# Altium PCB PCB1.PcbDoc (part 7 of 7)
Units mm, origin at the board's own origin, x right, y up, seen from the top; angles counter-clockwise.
Board outline 139.9 x 46.81 mm, 2 copper layers (Top Layer, Bottom Layer); 0 components, 100 nets, 100 pads, 0 vias.
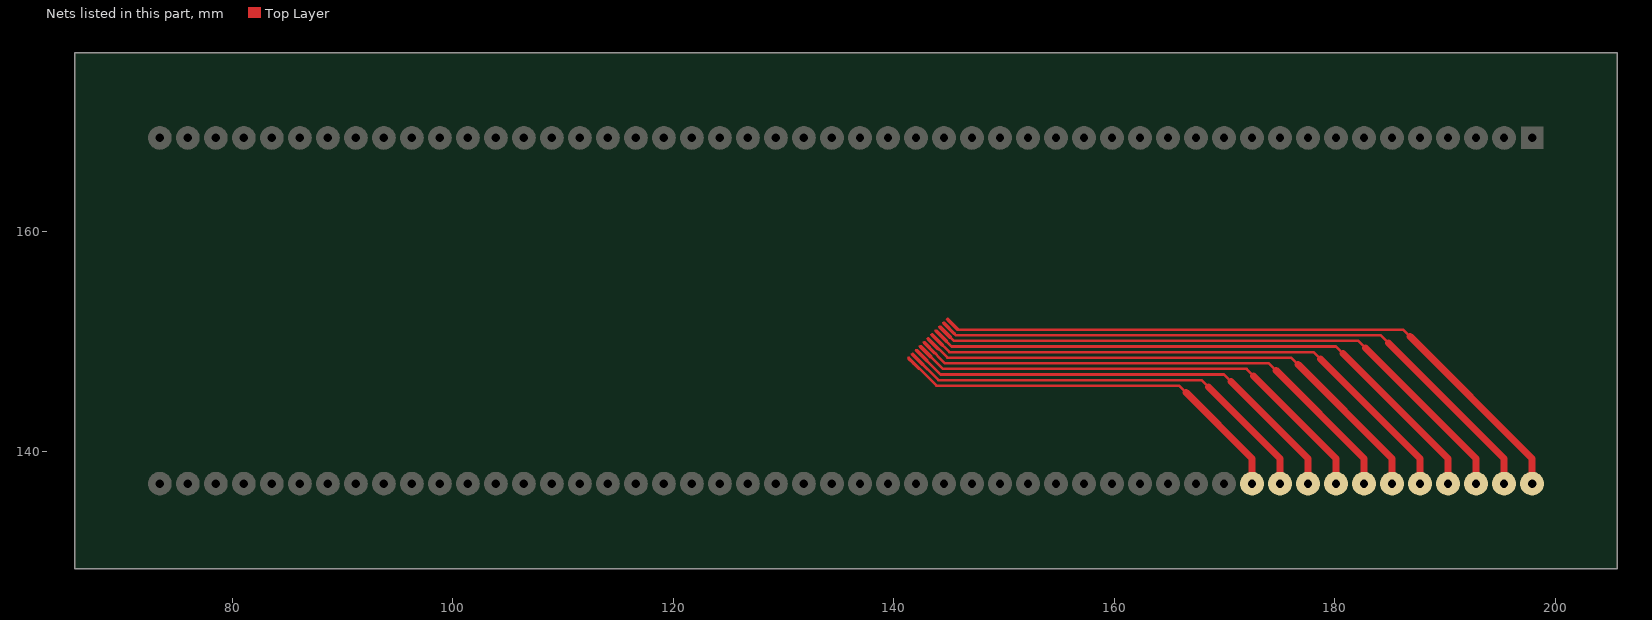
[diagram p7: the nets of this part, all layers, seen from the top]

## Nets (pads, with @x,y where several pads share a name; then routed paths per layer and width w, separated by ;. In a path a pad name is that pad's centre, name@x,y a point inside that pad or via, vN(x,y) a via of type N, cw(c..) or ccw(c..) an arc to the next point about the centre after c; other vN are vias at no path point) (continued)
$Net89: pad.1@172.487,137.086 | length 60.5
  Top Layer w0.03: 141.243,148.47 141.512,148.47 ; 141.245,148.455 141.527,148.455 ; 141.248,148.44 141.542,148.44 ; 141.255,148.424 141.558,148.424 ; 141.258,148.516 141.466,148.516 ; 141.268,148.409 141.573,148.409 ; 141.283,148.394 141.588,148.394 ; 141.283,148.546 141.436,148.546 ; 141.298,148.379 141.603,148.379 ; 141.301,148.561 141.42,148.561 ; 141.314,148.363 141.618,148.363 ; 141.324,148.577 141.397,148.577 ; 141.329,148.348 141.634,148.348 ; 141.344,148.333 141.649,148.333 ; 141.359,148.318 141.664,148.318 ; 141.375,148.302 141.679,148.302 ; 141.39,148.287 141.695,148.287 ; 141.405,148.272 141.71,148.272 ; 141.42,148.257 141.725,148.257 ; 141.436,148.241 141.74,148.241 ; 141.451,148.226 141.756,148.226 ; 141.451,148.531 141.268,148.531 ; 141.466,148.211 141.771,148.211 ; 141.481,148.196 141.786,148.196 ; 141.481,148.501 141.248,148.501 ; 141.497,148.18 141.801,148.18 ; 141.497,148.485 141.243,148.485 ; 141.512,148.165 141.817,148.165 ; 141.527,148.15 141.832,148.15 ; 141.542,148.135 141.847,148.135 ; 141.558,148.12 141.862,148.12 ; 141.573,148.104 141.878,148.104 ; 141.588,148.089 141.893,148.089 ; 141.603,148.074 141.905,148.074 ; 141.618,148.059 141.921,148.059 ; 141.634,148.043 141.936,148.043 ; 141.649,148.028 141.951,148.028 ; 141.664,148.013 141.966,148.013 ; 141.679,147.998 141.982,147.998 ; 141.695,147.982 141.997,147.982 ; 141.71,147.967 142.012,147.967 ; 141.725,147.952 142.027,147.952 ; 141.738,147.937 142.043,147.937 ; 141.753,147.921 142.058,147.921 ; 141.768,147.906 142.073,147.906 ; 141.784,147.891 142.088,147.891 ; 141.799,147.876 142.104,147.876 ; 141.814,147.86 142.119,147.86 ; 141.829,147.845 142.134,147.845 ; 141.845,147.83 142.149,147.83 ; 141.86,147.815 142.165,147.815 ; 141.875,147.799 142.18,147.799 ; 141.89,147.784 142.195,147.784 ; 141.905,147.769 142.21,147.769 ; 141.921,147.754 142.226,147.754 ; 141.936,147.739 142.241,147.739 ; 141.951,147.723 142.256,147.723 ; 141.966,147.708 142.271,147.708 ; 141.982,147.693 142.286,147.693 ; 141.997,147.678 142.302,147.678 ; 142.012,147.662 142.317,147.662 ; 142.027,147.647 142.332,147.647 ; 142.043,147.632 142.347,147.632 ; 142.058,147.617 142.363,147.617 ; 142.073,147.601 142.37,147.601 ; 142.088,147.586 142.375,147.586 ; 142.104,147.571 142.378,147.571 ; 142.119,147.556 142.378,147.556 ; 142.134,147.54 142.373,147.54 ; 142.149,147.525 142.365,147.525 ; 142.165,147.51 142.355,147.51 ; 142.18,147.495 142.34,147.495 ; 142.195,147.479 142.325,147.479 ; 142.304,147.464 142.21,147.464 ; 141.243,148.485 141.248,148.501 ; 141.243,148.485 141.24,148.467 141.248,148.434 141.255,148.422 142.198,147.474 142.21,147.464 ; 141.248,148.501 141.268,148.531 ; 141.268,148.531 141.296,148.559 141.326,148.579 141.342,148.584 141.359,148.587 141.392,148.579 141.408,148.572 141.42,148.561 ; 141.42,148.561 142.363,147.614 142.37,147.601 ; 142.21,147.464 142.226,147.457 142.259,147.449 142.276,147.451 142.292,147.457 142.322,147.477 142.35,147.505 142.37,147.535 142.375,147.551 142.378,147.568 142.37,147.601
  Top Layer w0.241: 141.809,148.018 143.851,145.976 165.883,145.976 166.518,145.341
  Top Layer w0.635: 166.518,145.341 172.487,139.372 pad.1@172.487,137.086
$Net90: pad.1@175.025,137.086 | length 62.8
  Top Layer w0.03: 141.596,148.826 141.865,148.826 ; 141.598,148.81 141.88,148.81 ; 141.601,148.795 141.895,148.795 ; 141.608,148.78 141.911,148.78 ; 141.611,148.871 141.819,148.871 ; 141.621,148.765 141.926,148.765 ; 141.636,148.749 141.941,148.749 ; 141.636,148.902 141.789,148.902 ; 141.651,148.734 141.956,148.734 ; 141.654,148.917 141.773,148.917 ; 141.667,148.719 141.972,148.719 ; 141.677,148.932 141.751,148.932 ; 141.682,148.704 141.987,148.704 ; 141.697,148.688 142.002,148.688 ; 141.712,148.673 142.017,148.673 ; 141.728,148.658 142.032,148.658 ; 141.743,148.643 142.048,148.643 ; 141.758,148.628 142.063,148.628 ; 141.773,148.612 142.078,148.612 ; 141.789,148.597 142.093,148.597 ; 141.804,148.582 142.109,148.582 ; 141.804,148.887 141.621,148.887 ; 141.819,148.567 142.124,148.567 ; 141.834,148.551 142.139,148.551 ; 141.834,148.856 141.601,148.856 ; 141.85,148.536 142.154,148.536 ; 141.85,148.841 141.596,148.841 ; 141.865,148.521 142.17,148.521 ; 141.88,148.506 142.185,148.506 ; 141.895,148.49 142.2,148.49 ; 141.911,148.475 142.215,148.475 ; 141.926,148.46 142.231,148.46 ; 141.941,148.445 142.246,148.445 ; 141.956,148.429 142.259,148.429 ; 141.972,148.414 142.274,148.414 ; 141.987,148.399 142.289,148.399 ; 142.002,148.384 142.304,148.384 ; 142.017,148.368 142.32,148.368 ; 142.032,148.353 142.335,148.353 ; 142.048,148.338 142.35,148.338 ; 142.063,148.323 142.365,148.323 ; 142.078,148.307 142.38,148.307 ; 142.091,148.292 142.396,148.292 ; 142.106,148.277 142.411,148.277 ; 142.121,148.262 142.426,148.262 ; 142.137,148.247 142.441,148.247 ; 142.152,148.231 142.457,148.231 ; 142.167,148.216 142.472,148.216 ; 142.182,148.201 142.487,148.201 ; 142.198,148.186 142.502,148.186 ; 142.213,148.17 142.518,148.17 ; 142.228,148.155 142.533,148.155 ; 142.243,148.14 142.548,148.14 ; 142.259,148.125 142.563,148.125 ; 142.274,148.109 142.579,148.109 ; 142.289,148.094 142.594,148.094 ; 142.304,148.079 142.609,148.079 ; 142.32,148.064 142.624,148.064 ; 142.335,148.048 142.64,148.048 ; 142.35,148.033 142.655,148.033 ; 142.365,148.018 142.67,148.018 ; 142.38,148.003 142.685,148.003 ; 142.396,147.987 142.701,147.987 ; 142.411,147.972 142.716,147.972 ; 142.426,147.957 142.723,147.957 ; 142.441,147.942 142.728,147.942 ; 142.457,147.926 142.731,147.926 ; 142.472,147.911 142.731,147.911 ; 142.487,147.896 142.726,147.896 ; 142.502,147.881 142.718,147.881 ; 142.518,147.866 142.708,147.866 ; 142.533,147.85 142.693,147.85 ; 142.548,147.835 142.678,147.835 ; 142.657,147.82 142.563,147.82 ; 141.596,148.841 141.601,148.856 ; 141.596,148.841 141.593,148.823 141.601,148.79 141.608,148.777 142.551,147.83 142.563,147.82 ; 141.601,148.856 141.621,148.887 ; 141.621,148.887 141.649,148.915 141.679,148.935 141.695,148.94 141.712,148.942 141.745,148.935 141.761,148.927 141.773,148.917 ; 141.773,148.917 142.716,147.97 142.723,147.957 ; 142.563,147.82 142.579,147.812 142.612,147.805 142.629,147.807 142.645,147.812 142.675,147.832 142.703,147.86 142.723,147.891 142.728,147.906 142.731,147.924 142.723,147.957
  Top Layer w0.241: 142.162,148.374 144.052,146.484 167.915,146.484 168.55,145.849
  Top Layer w0.635: 168.55,145.849 175.025,139.372 pad.1@175.025,137.086
$Net91: pad.1@177.565,137.086 | length 65.1
  Top Layer w0.03: 141.949,149.179 142.218,149.179 ; 141.951,149.163 142.233,149.163 ; 141.954,149.148 142.248,149.148 ; 141.961,149.133 142.264,149.133 ; 141.964,149.224 142.172,149.224 ; 141.974,149.118 142.279,149.118 ; 141.989,149.102 142.294,149.102 ; 141.989,149.255 142.142,149.255 ; 142.005,149.087 142.309,149.087 ; 142.007,149.27 142.126,149.27 ; 142.02,149.072 142.325,149.072 ; 142.03,149.285 142.104,149.285 ; 142.035,149.057 142.34,149.057 ; 142.05,149.042 142.355,149.042 ; 142.066,149.026 142.37,149.026 ; 142.081,149.011 142.386,149.011 ; 142.096,148.996 142.401,148.996 ; 142.111,148.981 142.416,148.981 ; 142.126,148.965 142.431,148.965 ; 142.142,148.95 142.447,148.95 ; 142.157,148.935 142.462,148.935 ; 142.157,149.24 141.974,149.24 ; 142.172,148.92 142.477,148.92 ; 142.187,148.904 142.492,148.904 ; 142.187,149.209 141.954,149.209 ; 142.203,148.889 142.507,148.889 ; 142.203,149.194 141.949,149.194 ; 142.218,148.874 142.523,148.874 ; 142.233,148.859 142.538,148.859 ; 142.248,148.843 142.553,148.843 ; 142.264,148.828 142.568,148.828 ; 142.279,148.813 142.584,148.813 ; 142.294,148.798 142.599,148.798 ; 142.309,148.782 142.612,148.782 ; 142.325,148.767 142.627,148.767 ; 142.34,148.752 142.642,148.752 ; 142.355,148.737 142.657,148.737 ; 142.37,148.721 142.673,148.721 ; 142.386,148.706 142.688,148.706 ; 142.401,148.691 142.703,148.691 ; 142.416,148.676 142.718,148.676 ; 142.431,148.661 142.734,148.661 ; 142.444,148.645 142.749,148.645 ; 142.459,148.63 142.764,148.63 ; 142.474,148.615 142.779,148.615 ; 142.49,148.6 142.794,148.6 ; 142.505,148.584 142.81,148.584 ; 142.52,148.569 142.825,148.569 ; 142.535,148.554 142.84,148.554 ; 142.551,148.539 142.855,148.539 ; 142.566,148.523 142.871,148.523 ; 142.581,148.508 142.886,148.508 ; 142.596,148.493 142.901,148.493 ; 142.612,148.478 142.916,148.478 ; 142.627,148.462 142.932,148.462 ; 142.642,148.447 142.947,148.447 ; 142.657,148.432 142.962,148.432 ; 142.673,148.417 142.977,148.417 ; 142.688,148.401 142.993,148.401 ; 142.703,148.386 143.008,148.386 ; 142.718,148.371 143.023,148.371 ; 142.734,148.356 143.038,148.356 ; 142.749,148.34 143.054,148.34 ; 142.764,148.325 143.069,148.325 ; 142.779,148.31 143.076,148.31 ; 142.794,148.295 143.082,148.295 ; 142.81,148.28 143.084,148.28 ; 142.825,148.264 143.084,148.264 ; 142.84,148.249 143.079,148.249 ; 142.855,148.234 143.071,148.234 ; 142.871,148.219 143.061,148.219 ; 142.886,148.203 143.046,148.203 ; 142.901,148.188 143.031,148.188 ; 143.01,148.173 142.916,148.173 ; 141.949,149.194 141.954,149.209 ; 141.949,149.194 141.946,149.176 141.954,149.143 141.961,149.13 142.904,148.183 142.916,148.173 ; 141.954,149.209 141.974,149.24 ; 141.974,149.24 142.002,149.268 142.032,149.288 142.048,149.293 142.066,149.296 142.099,149.288 142.114,149.28 142.126,149.27 ; 142.126,149.27 143.069,148.323 143.076,148.31 ; 142.916,148.173 142.932,148.165 142.965,148.158 142.982,148.16 142.998,148.165 143.028,148.186 143.056,148.213 143.076,148.244 143.082,148.259 143.084,148.277 143.076,148.31
  Top Layer w0.241: 142.515,148.727 144.25,146.992 169.947,146.992 170.582,146.357
  Top Layer w0.635: 170.582,146.357 177.565,139.372 pad.1@177.565,137.086
$Net92: pad.1@180.105,137.086 | length 67.5
  Top Layer w0.03: 142.302,149.532 142.571,149.532 ; 142.304,149.517 142.586,149.517 ; 142.307,149.501 142.601,149.501 ; 142.314,149.486 142.617,149.486 ; 142.317,149.577 142.525,149.577 ; 142.327,149.471 142.632,149.471 ; 142.342,149.456 142.647,149.456 ; 142.342,149.608 142.495,149.608 ; 142.358,149.44 142.662,149.44 ; 142.36,149.623 142.48,149.623 ; 142.373,149.425 142.678,149.425 ; 142.383,149.638 142.457,149.638 ; 142.388,149.41 142.693,149.41 ; 142.403,149.395 142.708,149.395 ; 142.419,149.379 142.723,149.379 ; 142.434,149.364 142.739,149.364 ; 142.449,149.349 142.754,149.349 ; 142.464,149.334 142.769,149.334 ; 142.48,149.318 142.784,149.318 ; 142.495,149.303 142.8,149.303 ; 142.51,149.288 142.815,149.288 ; 142.51,149.593 142.327,149.593 ; 142.525,149.273 142.83,149.273 ; 142.54,149.257 142.845,149.257 ; 142.54,149.562 142.307,149.562 ; 142.556,149.242 142.861,149.242 ; 142.556,149.547 142.302,149.547 ; 142.571,149.227 142.876,149.227 ; 142.586,149.212 142.891,149.212 ; 142.601,149.196 142.906,149.196 ; 142.617,149.181 142.921,149.181 ; 142.632,149.166 142.937,149.166 ; 142.647,149.151 142.952,149.151 ; 142.662,149.136 142.965,149.136 ; 142.678,149.12 142.98,149.12 ; 142.693,149.105 142.995,149.105 ; 142.708,149.09 143.01,149.09 ; 142.723,149.075 143.026,149.075 ; 142.739,149.059 143.041,149.059 ; 142.754,149.044 143.056,149.044 ; 142.769,149.029 143.071,149.029 ; 142.784,149.014 143.087,149.014 ; 142.797,148.998 143.102,148.998 ; 142.812,148.983 143.117,148.983 ; 142.828,148.968 143.132,148.968 ; 142.843,148.953 143.148,148.953 ; 142.858,148.937 143.163,148.937 ; 142.873,148.922 143.178,148.922 ; 142.888,148.907 143.193,148.907 ; 142.904,148.892 143.209,148.892 ; 142.919,148.876 143.224,148.876 ; 142.934,148.861 143.239,148.861 ; 142.949,148.846 143.254,148.846 ; 142.965,148.831 143.269,148.831 ; 142.98,148.815 143.285,148.815 ; 142.995,148.8 143.3,148.8 ; 143.01,148.785 143.315,148.785 ; 143.026,148.77 143.33,148.77 ; 143.041,148.755 143.346,148.755 ; 143.056,148.739 143.361,148.739 ; 143.071,148.724 143.376,148.724 ; 143.087,148.709 143.391,148.709 ; 143.102,148.694 143.407,148.694 ; 143.117,148.678 143.422,148.678 ; 143.132,148.663 143.429,148.663 ; 143.148,148.648 143.435,148.648 ; 143.163,148.633 143.437,148.633 ; 143.178,148.617 143.437,148.617 ; 143.193,148.602 143.432,148.602 ; 143.209,148.587 143.424,148.587 ; 143.224,148.572 143.414,148.572 ; 143.239,148.556 143.399,148.556 ; 143.254,148.541 143.384,148.541 ; 143.363,148.526 143.269,148.526 ; 142.302,149.547 142.307,149.562 ; 142.302,149.547 142.299,149.529 142.307,149.496 142.314,149.483 143.257,148.536 143.269,148.526 ; 142.307,149.562 142.327,149.593 ; 142.327,149.593 142.355,149.621 142.386,149.641 142.401,149.646 142.419,149.649 142.452,149.641 142.467,149.633 142.48,149.623 ; 142.48,149.623 143.422,148.676 143.429,148.663 ; 143.269,148.526 143.285,148.518 143.318,148.511 143.336,148.513 143.351,148.518 143.381,148.539 143.409,148.567 143.429,148.597 143.435,148.612 143.437,148.63 143.429,148.663
  Top Layer w0.241: 142.868,149.08 144.448,147.5 171.979,147.5 172.614,146.865
  Top Layer w0.635: 172.614,146.865 180.105,139.372 pad.1@180.105,137.086
$Net93: pad.1@182.645,137.086 | length 69.8
  Top Layer w0.03: 142.655,149.885 142.924,149.885 ; 142.657,149.87 142.939,149.87 ; 142.66,149.854 142.955,149.854 ; 142.667,149.839 142.97,149.839 ; 142.67,149.931 142.878,149.931 ; 142.68,149.824 142.985,149.824 ; 142.695,149.809 143,149.809 ; 142.695,149.961 142.848,149.961 ; 142.711,149.793 143.015,149.793 ; 142.713,149.976 142.833,149.976 ; 142.726,149.778 143.031,149.778 ; 142.736,149.991 142.81,149.991 ; 142.741,149.763 143.046,149.763 ; 142.756,149.748 143.061,149.748 ; 142.772,149.732 143.076,149.732 ; 142.787,149.717 143.092,149.717 ; 142.802,149.702 143.107,149.702 ; 142.817,149.687 143.122,149.687 ; 142.833,149.671 143.137,149.671 ; 142.848,149.656 143.153,149.656 ; 142.863,149.641 143.168,149.641 ; 142.863,149.946 142.68,149.946 ; 142.878,149.626 143.183,149.626 ; 142.894,149.61 143.198,149.61 ; 142.894,149.915 142.66,149.915 ; 142.909,149.595 143.214,149.595 ; 142.909,149.9 142.655,149.9 ; 142.924,149.58 143.229,149.58 ; 142.939,149.565 143.244,149.565 ; 142.955,149.55 143.259,149.55 ; 142.97,149.534 143.275,149.534 ; 142.985,149.519 143.29,149.519 ; 143,149.504 143.305,149.504 ; 143.015,149.489 143.318,149.489 ; 143.031,149.473 143.333,149.473 ; 143.046,149.458 143.348,149.458 ; 143.061,149.443 143.363,149.443 ; 143.076,149.428 143.379,149.428 ; 143.092,149.412 143.394,149.412 ; 143.107,149.397 143.409,149.397 ; 143.122,149.382 143.424,149.382 ; 143.137,149.367 143.44,149.367 ; 143.15,149.351 143.455,149.351 ; 143.165,149.336 143.47,149.336 ; 143.181,149.321 143.485,149.321 ; 143.196,149.306 143.501,149.306 ; 143.211,149.29 143.516,149.29 ; 143.226,149.275 143.531,149.275 ; 143.242,149.26 143.546,149.26 ; 143.257,149.245 143.562,149.245 ; 143.272,149.229 143.577,149.229 ; 143.287,149.214 143.592,149.214 ; 143.302,149.199 143.607,149.199 ; 143.318,149.184 143.623,149.184 ; 143.333,149.169 143.638,149.169 ; 143.348,149.153 143.653,149.153 ; 143.363,149.138 143.668,149.138 ; 143.379,149.123 143.683,149.123 ; 143.394,149.108 143.699,149.108 ; 143.409,149.092 143.714,149.092 ; 143.424,149.077 143.729,149.077 ; 143.44,149.062 143.744,149.062 ; 143.455,149.047 143.76,149.047 ; 143.47,149.031 143.775,149.031 ; 143.485,149.016 143.783,149.016 ; 143.501,149.001 143.788,149.001 ; 143.516,148.986 143.79,148.986 ; 143.531,148.97 143.79,148.97 ; 143.546,148.955 143.785,148.955 ; 143.562,148.94 143.777,148.94 ; 143.577,148.925 143.767,148.925 ; 143.592,148.909 143.752,148.909 ; 143.607,148.894 143.737,148.894 ; 143.717,148.879 143.623,148.879 ; 142.655,149.9 142.66,149.915 ; 142.655,149.9 142.652,149.882 142.66,149.849 142.667,149.837 143.61,148.889 143.623,148.879 ; 142.66,149.915 142.68,149.946 ; 142.68,149.946 142.708,149.974 142.739,149.994 142.754,149.999 142.772,150.002 142.805,149.994 142.82,149.986 142.833,149.976 ; 142.833,149.976 143.775,149.029 143.783,149.016 ; 143.623,148.879 143.638,148.871 143.671,148.864 143.689,148.866 143.704,148.871 143.734,148.892 143.762,148.92 143.783,148.95 143.788,148.965 143.79,148.983 143.783,149.016
  Top Layer w0.241: 143.221,149.433 144.649,148.008 174.011,148.008 174.646,147.373
  Top Layer w0.635: 174.646,147.373 182.645,139.372 pad.1@182.645,137.086
$Net94: pad.1@185.185,137.086 | length 72.1
  Top Layer w0.03: 143.008,150.238 143.277,150.238 ; 143.01,150.223 143.292,150.223 ; 143.013,150.207 143.308,150.207 ; 143.021,150.192 143.323,150.192 ; 143.023,150.284 143.231,150.284 ; 143.033,150.177 143.338,150.177 ; 143.048,150.162 143.353,150.162 ; 143.048,150.314 143.201,150.314 ; 143.064,150.146 143.369,150.146 ; 143.066,150.329 143.186,150.329 ; 143.079,150.131 143.384,150.131 ; 143.089,150.345 143.163,150.345 ; 143.094,150.116 143.399,150.116 ; 143.109,150.101 143.414,150.101 ; 143.125,150.085 143.429,150.085 ; 143.14,150.07 143.445,150.07 ; 143.155,150.055 143.46,150.055 ; 143.17,150.04 143.475,150.04 ; 143.186,150.025 143.49,150.025 ; 143.201,150.009 143.506,150.009 ; 143.216,149.994 143.521,149.994 ; 143.216,150.299 143.033,150.299 ; 143.231,149.979 143.536,149.979 ; 143.247,149.964 143.551,149.964 ; 143.247,150.268 143.013,150.268 ; 143.262,149.948 143.567,149.948 ; 143.262,150.253 143.008,150.253 ; 143.277,149.933 143.582,149.933 ; 143.292,149.918 143.597,149.918 ; 143.308,149.903 143.612,149.903 ; 143.323,149.887 143.628,149.887 ; 143.338,149.872 143.643,149.872 ; 143.353,149.857 143.658,149.857 ; 143.369,149.842 143.671,149.842 ; 143.384,149.826 143.686,149.826 ; 143.399,149.811 143.701,149.811 ; 143.414,149.796 143.717,149.796 ; 143.429,149.781 143.732,149.781 ; 143.445,149.765 143.747,149.765 ; 143.46,149.75 143.762,149.75 ; 143.475,149.735 143.777,149.735 ; 143.49,149.72 143.793,149.72 ; 143.503,149.704 143.808,149.704 ; 143.518,149.689 143.823,149.689 ; 143.534,149.674 143.838,149.674 ; 143.549,149.659 143.854,149.659 ; 143.564,149.644 143.869,149.644 ; 143.579,149.628 143.884,149.628 ; 143.595,149.613 143.899,149.613 ; 143.61,149.598 143.915,149.598 ; 143.625,149.583 143.93,149.583 ; 143.64,149.567 143.945,149.567 ; 143.656,149.552 143.96,149.552 ; 143.671,149.537 143.976,149.537 ; 143.686,149.522 143.991,149.522 ; 143.701,149.506 144.006,149.506 ; 143.717,149.491 144.021,149.491 ; 143.732,149.476 144.037,149.476 ; 143.747,149.461 144.052,149.461 ; 143.762,149.445 144.067,149.445 ; 143.777,149.43 144.082,149.43 ; 143.793,149.415 144.098,149.415 ; 143.808,149.4 144.113,149.4 ; 143.823,149.384 144.128,149.384 ; 143.838,149.369 144.136,149.369 ; 143.854,149.354 144.141,149.354 ; 143.869,149.339 144.143,149.339 ; 143.884,149.323 144.143,149.323 ; 143.899,149.308 144.138,149.308 ; 143.915,149.293 144.131,149.293 ; 143.93,149.278 144.12,149.278 ; 143.945,149.263 144.105,149.263 ; 143.96,149.247 144.09,149.247 ; 144.07,149.232 143.976,149.232 ; 143.008,150.253 143.013,150.268 ; 143.008,150.253 143.005,150.235 143.013,150.202 143.021,150.19 143.963,149.242 143.976,149.232 ; 143.013,150.268 143.033,150.299 ; 143.033,150.299 143.061,150.327 143.092,150.347 143.107,150.352 143.125,150.355 143.158,150.347 143.173,150.339 143.186,150.329 ; 143.186,150.329 144.128,149.382 144.136,149.369 ; 143.976,149.232 143.991,149.224 144.024,149.217 144.042,149.219 144.057,149.224 144.087,149.245 144.115,149.273 144.136,149.303 144.141,149.318 144.143,149.336 144.136,149.369
  Top Layer w0.241: 143.574,149.786 144.847,148.516 176.041,148.516 176.676,147.881
  Top Layer w0.635: 176.676,147.881 185.185,139.372 pad.1@185.185,137.086
$Net95: pad.1@187.725,137.086 | length 74.5
  Top Layer w0.03: 143.363,150.593 143.633,150.593 ; 143.366,150.578 143.648,150.578 ; 143.369,150.563 143.663,150.563 ; 143.376,150.548 143.678,150.548 ; 143.379,150.639 143.587,150.639 ; 143.389,150.533 143.694,150.533 ; 143.404,150.517 143.709,150.517 ; 143.404,150.67 143.556,150.67 ; 143.419,150.502 143.724,150.502 ; 143.422,150.685 143.541,150.685 ; 143.435,150.487 143.739,150.487 ; 143.445,150.7 143.518,150.7 ; 143.45,150.472 143.755,150.472 ; 143.465,150.456 143.77,150.456 ; 143.48,150.441 143.785,150.441 ; 143.496,150.426 143.8,150.426 ; 143.511,150.411 143.816,150.411 ; 143.526,150.395 143.831,150.395 ; 143.541,150.38 143.846,150.38 ; 143.556,150.365 143.861,150.365 ; 143.572,150.35 143.877,150.35 ; 143.572,150.654 143.389,150.654 ; 143.587,150.334 143.892,150.334 ; 143.602,150.319 143.907,150.319 ; 143.602,150.624 143.369,150.624 ; 143.617,150.304 143.922,150.304 ; 143.617,150.609 143.363,150.609 ; 143.633,150.289 143.937,150.289 ; 143.648,150.273 143.953,150.273 ; 143.663,150.258 143.968,150.258 ; 143.678,150.243 143.983,150.243 ; 143.694,150.228 143.998,150.228 ; 143.709,150.212 144.014,150.212 ; 143.724,150.197 144.026,150.197 ; 143.739,150.182 144.042,150.182 ; 143.755,150.167 144.057,150.167 ; 143.77,150.152 144.072,150.152 ; 143.785,150.136 144.087,150.136 ; 143.8,150.121 144.103,150.121 ; 143.816,150.106 144.118,150.106 ; 143.831,150.091 144.133,150.091 ; 143.846,150.075 144.148,150.075 ; 143.859,150.06 144.164,150.06 ; 143.874,150.045 144.179,150.045 ; 143.889,150.03 144.194,150.03 ; 143.904,150.014 144.209,150.014 ; 143.92,149.999 144.225,149.999 ; 143.935,149.984 144.24,149.984 ; 143.95,149.969 144.255,149.969 ; 143.965,149.953 144.27,149.953 ; 143.981,149.938 144.285,149.938 ; 143.996,149.923 144.301,149.923 ; 144.011,149.908 144.316,149.908 ; 144.026,149.892 144.331,149.892 ; 144.042,149.877 144.346,149.877 ; 144.057,149.862 144.362,149.862 ; 144.072,149.847 144.377,149.847 ; 144.087,149.831 144.392,149.831 ; 144.103,149.816 144.407,149.816 ; 144.118,149.801 144.423,149.801 ; 144.133,149.786 144.438,149.786 ; 144.148,149.771 144.453,149.771 ; 144.164,149.755 144.468,149.755 ; 144.179,149.74 144.484,149.74 ; 144.194,149.725 144.491,149.725 ; 144.209,149.71 144.496,149.71 ; 144.225,149.694 144.499,149.694 ; 144.24,149.679 144.499,149.679 ; 144.255,149.664 144.494,149.664 ; 144.27,149.649 144.486,149.649 ; 144.285,149.633 144.476,149.633 ; 144.301,149.618 144.461,149.618 ; 144.316,149.603 144.445,149.603 ; 144.425,149.588 144.331,149.588 ; 143.363,150.609 143.369,150.624 ; 143.363,150.609 143.361,150.591 143.369,150.558 143.376,150.545 144.318,149.598 144.331,149.588 ; 143.369,150.624 143.389,150.654 ; 143.389,150.654 143.417,150.682 143.447,150.703 143.463,150.708 143.48,150.71 143.513,150.703 143.529,150.695 143.541,150.685 ; 143.541,150.685 144.484,149.737 144.491,149.725 ; 144.331,149.588 144.346,149.58 144.379,149.572 144.397,149.575 144.412,149.58 144.443,149.6 144.471,149.628 144.491,149.659 144.496,149.674 144.499,149.692 144.491,149.725
  Top Layer w0.241: 143.93,150.141 145.047,149.024 178.073,149.024 178.708,148.389
  Top Layer w0.635: 178.708,148.389 187.725,139.372 pad.1@187.725,137.086
$Net96: pad.1@190.265,137.086 | length 76.8
  Top Layer w0.03: 143.717,150.947 143.986,150.947 ; 143.719,150.931 144.001,150.931 ; 143.722,150.916 144.016,150.916 ; 143.729,150.901 144.031,150.901 ; 143.732,150.992 143.94,150.992 ; 143.742,150.886 144.047,150.886 ; 143.757,150.87 144.062,150.87 ; 143.757,151.023 143.91,151.023 ; 143.772,150.855 144.077,150.855 ; 143.775,151.038 143.894,151.038 ; 143.788,150.84 144.092,150.84 ; 143.798,151.053 143.871,151.053 ; 143.803,150.825 144.108,150.825 ; 143.818,150.809 144.123,150.809 ; 143.833,150.794 144.138,150.794 ; 143.849,150.779 144.153,150.779 ; 143.864,150.764 144.169,150.764 ; 143.879,150.748 144.184,150.748 ; 143.894,150.733 144.199,150.733 ; 143.91,150.718 144.214,150.718 ; 143.925,150.703 144.23,150.703 ; 143.925,151.007 143.742,151.007 ; 143.94,150.687 144.245,150.687 ; 143.955,150.672 144.26,150.672 ; 143.955,150.977 143.722,150.977 ; 143.971,150.657 144.275,150.657 ; 143.971,150.962 143.717,150.962 ; 143.986,150.642 144.291,150.642 ; 144.001,150.626 144.306,150.626 ; 144.016,150.611 144.321,150.611 ; 144.031,150.596 144.336,150.596 ; 144.047,150.581 144.352,150.581 ; 144.062,150.566 144.367,150.566 ; 144.077,150.55 144.379,150.55 ; 144.092,150.535 144.395,150.535 ; 144.108,150.52 144.41,150.52 ; 144.123,150.505 144.425,150.505 ; 144.138,150.489 144.44,150.489 ; 144.153,150.474 144.456,150.474 ; 144.169,150.459 144.471,150.459 ; 144.184,150.444 144.486,150.444 ; 144.199,150.428 144.501,150.428 ; 144.212,150.413 144.517,150.413 ; 144.227,150.398 144.532,150.398 ; 144.242,150.383 144.547,150.383 ; 144.258,150.367 144.562,150.367 ; 144.273,150.352 144.578,150.352 ; 144.288,150.337 144.593,150.337 ; 144.303,150.322 144.608,150.322 ; 144.318,150.306 144.623,150.306 ; 144.334,150.291 144.639,150.291 ; 144.349,150.276 144.654,150.276 ; 144.364,150.261 144.669,150.261 ; 144.379,150.245 144.684,150.245 ; 144.395,150.23 144.699,150.23 ; 144.41,150.215 144.715,150.215 ; 144.425,150.2 144.73,150.2 ; 144.44,150.185 144.745,150.185 ; 144.456,150.169 144.76,150.169 ; 144.471,150.154 144.776,150.154 ; 144.486,150.139 144.791,150.139 ; 144.501,150.124 144.806,150.124 ; 144.517,150.108 144.821,150.108 ; 144.532,150.093 144.837,150.093 ; 144.547,150.078 144.844,150.078 ; 144.562,150.063 144.849,150.063 ; 144.578,150.047 144.852,150.047 ; 144.593,150.032 144.852,150.032 ; 144.608,150.017 144.847,150.017 ; 144.623,150.002 144.839,150.002 ; 144.639,149.986 144.829,149.986 ; 144.654,149.971 144.814,149.971 ; 144.669,149.956 144.799,149.956 ; 144.778,149.941 144.684,149.941 ; 143.717,150.962 143.722,150.977 ; 143.717,150.962 143.714,150.944 143.722,150.911 143.729,150.898 144.672,149.951 144.684,149.941 ; 143.722,150.977 143.742,151.007 ; 143.742,151.007 143.77,151.035 143.8,151.056 143.816,151.061 143.833,151.063 143.866,151.056 143.882,151.048 143.894,151.038 ; 143.894,151.038 144.837,150.091 144.844,150.078 ; 144.684,149.941 144.699,149.933 144.733,149.925 144.75,149.928 144.766,149.933 144.796,149.953 144.824,149.981 144.844,150.012 144.849,150.027 144.852,150.045 144.844,150.078
  Top Layer w0.241: 144.283,150.494 145.246,149.532 180.105,149.532 180.74,148.897
  Top Layer w0.635: 180.74,148.897 190.265,139.372 pad.1@190.265,137.086
$Net97: pad.1@192.805,137.086 | length 79.1
  Top Layer w0.03: 144.07,151.3 144.339,151.3 ; 144.072,151.284 144.354,151.284 ; 144.075,151.269 144.369,151.269 ; 144.082,151.254 144.385,151.254 ; 144.085,151.345 144.293,151.345 ; 144.095,151.239 144.4,151.239 ; 144.11,151.223 144.415,151.223 ; 144.11,151.376 144.263,151.376 ; 144.125,151.208 144.43,151.208 ; 144.128,151.391 144.247,151.391 ; 144.141,151.193 144.445,151.193 ; 144.151,151.406 144.225,151.406 ; 144.156,151.178 144.461,151.178 ; 144.171,151.162 144.476,151.162 ; 144.186,151.147 144.491,151.147 ; 144.202,151.132 144.506,151.132 ; 144.217,151.117 144.522,151.117 ; 144.232,151.101 144.537,151.101 ; 144.247,151.086 144.552,151.086 ; 144.263,151.071 144.567,151.071 ; 144.278,151.056 144.583,151.056 ; 144.278,151.361 144.095,151.361 ; 144.293,151.041 144.598,151.041 ; 144.308,151.025 144.613,151.025 ; 144.308,151.33 144.075,151.33 ; 144.324,151.01 144.628,151.01 ; 144.324,151.315 144.07,151.315 ; 144.339,150.995 144.644,150.995 ; 144.354,150.98 144.659,150.98 ; 144.369,150.964 144.674,150.964 ; 144.385,150.949 144.689,150.949 ; 144.4,150.934 144.705,150.934 ; 144.415,150.919 144.72,150.919 ; 144.43,150.903 144.733,150.903 ; 144.445,150.888 144.748,150.888 ; 144.461,150.873 144.763,150.873 ; 144.476,150.858 144.778,150.858 ; 144.491,150.842 144.793,150.842 ; 144.506,150.827 144.809,150.827 ; 144.522,150.812 144.824,150.812 ; 144.537,150.797 144.839,150.797 ; 144.552,150.781 144.854,150.781 ; 144.565,150.766 144.87,150.766 ; 144.58,150.751 144.885,150.751 ; 144.595,150.736 144.9,150.736 ; 144.611,150.72 144.915,150.72 ; 144.626,150.705 144.931,150.705 ; 144.641,150.69 144.946,150.69 ; 144.656,150.675 144.961,150.675 ; 144.672,150.66 144.976,150.66 ; 144.687,150.644 144.992,150.644 ; 144.702,150.629 145.007,150.629 ; 144.717,150.614 145.022,150.614 ; 144.733,150.599 145.037,150.599 ; 144.748,150.583 145.053,150.583 ; 144.763,150.568 145.068,150.568 ; 144.778,150.553 145.083,150.553 ; 144.793,150.538 145.098,150.538 ; 144.809,150.522 145.114,150.522 ; 144.824,150.507 145.129,150.507 ; 144.839,150.492 145.144,150.492 ; 144.854,150.477 145.159,150.477 ; 144.87,150.461 145.174,150.461 ; 144.885,150.446 145.19,150.446 ; 144.9,150.431 145.197,150.431 ; 144.915,150.416 145.202,150.416 ; 144.931,150.4 145.205,150.4 ; 144.946,150.385 145.205,150.385 ; 144.961,150.37 145.2,150.37 ; 144.976,150.355 145.192,150.355 ; 144.992,150.339 145.182,150.339 ; 145.007,150.324 145.167,150.324 ; 145.022,150.309 145.152,150.309 ; 145.131,150.294 145.037,150.294 ; 144.07,151.315 144.075,151.33 ; 144.07,151.315 144.067,151.297 144.075,151.264 144.082,151.251 145.025,150.304 145.037,150.294 ; 144.075,151.33 144.095,151.361 ; 144.095,151.361 144.123,151.388 144.153,151.409 144.169,151.414 144.186,151.416 144.219,151.409 144.235,151.401 144.247,151.391 ; 144.247,151.391 145.19,150.444 145.197,150.431 ; 145.037,150.294 145.053,150.286 145.086,150.279 145.103,150.281 145.119,150.286 145.149,150.306 145.177,150.334 145.197,150.365 145.202,150.38 145.205,150.398 145.197,150.431
  Top Layer w0.241: 144.636,150.847 145.444,150.04 182.137,150.04 182.772,149.405
  Top Layer w0.635: 182.772,149.405 192.805,139.372 pad.1@192.805,137.086
$Net98: pad.1@195.345,137.086 | length 81.5
  Top Layer w0.03: 144.423,151.653 144.692,151.653 ; 144.425,151.637 144.707,151.637 ; 144.428,151.622 144.722,151.622 ; 144.435,151.607 144.738,151.607 ; 144.438,151.698 144.646,151.698 ; 144.448,151.592 144.753,151.592 ; 144.463,151.576 144.768,151.576 ; 144.463,151.729 144.616,151.729 ; 144.479,151.561 144.783,151.561 ; 144.481,151.744 144.6,151.744 ; 144.494,151.546 144.799,151.546 ; 144.504,151.759 144.578,151.759 ; 144.509,151.531 144.814,151.531 ; 144.524,151.515 144.829,151.515 ; 144.539,151.5 144.844,151.5 ; 144.555,151.485 144.86,151.485 ; 144.57,151.47 144.875,151.47 ; 144.585,151.455 144.89,151.455 ; 144.6,151.439 144.905,151.439 ; 144.616,151.424 144.92,151.424 ; 144.631,151.409 144.936,151.409 ; 144.631,151.714 144.448,151.714 ; 144.646,151.394 144.951,151.394 ; 144.661,151.378 144.966,151.378 ; 144.661,151.683 144.428,151.683 ; 144.677,151.363 144.981,151.363 ; 144.677,151.668 144.423,151.668 ; 144.692,151.348 144.997,151.348 ; 144.707,151.333 145.012,151.333 ; 144.722,151.317 145.027,151.317 ; 144.738,151.302 145.042,151.302 ; 144.753,151.287 145.058,151.287 ; 144.768,151.272 145.073,151.272 ; 144.783,151.256 145.086,151.256 ; 144.799,151.241 145.101,151.241 ; 144.814,151.226 145.116,151.226 ; 144.829,151.211 145.131,151.211 ; 144.844,151.195 145.147,151.195 ; 144.86,151.18 145.162,151.18 ; 144.875,151.165 145.177,151.165 ; 144.89,151.15 145.192,151.15 ; 144.905,151.134 145.207,151.134 ; 144.918,151.119 145.223,151.119 ; 144.933,151.104 145.238,151.104 ; 144.948,151.089 145.253,151.089 ; 144.964,151.074 145.268,151.074 ; 144.979,151.058 145.284,151.058 ; 144.994,151.043 145.299,151.043 ; 145.009,151.028 145.314,151.028 ; 145.025,151.013 145.329,151.013 ; 145.04,150.997 145.345,150.997 ; 145.055,150.982 145.36,150.982 ; 145.07,150.967 145.375,150.967 ; 145.086,150.952 145.39,150.952 ; 145.101,150.936 145.406,150.936 ; 145.116,150.921 145.421,150.921 ; 145.131,150.906 145.436,150.906 ; 145.147,150.891 145.451,150.891 ; 145.162,150.875 145.467,150.875 ; 145.177,150.86 145.482,150.86 ; 145.192,150.845 145.497,150.845 ; 145.207,150.83 145.512,150.83 ; 145.223,150.814 145.528,150.814 ; 145.238,150.799 145.543,150.799 ; 145.253,150.784 145.55,150.784 ; 145.268,150.769 145.555,150.769 ; 145.284,150.753 145.558,150.753 ; 145.299,150.738 145.558,150.738 ; 145.314,150.723 145.553,150.723 ; 145.329,150.708 145.545,150.708 ; 145.345,150.693 145.535,150.693 ; 145.36,150.677 145.52,150.677 ; 145.375,150.662 145.505,150.662 ; 145.484,150.647 145.39,150.647 ; 144.423,151.668 144.428,151.683 ; 144.423,151.668 144.42,151.65 144.428,151.617 144.435,151.604 145.378,150.657 145.39,150.647 ; 144.428,151.683 144.448,151.714 ; 144.448,151.714 144.476,151.742 144.506,151.762 144.522,151.767 144.539,151.769 144.572,151.762 144.588,151.754 144.6,151.744 ; 144.6,151.744 145.543,150.797 145.55,150.784 ; 145.39,150.647 145.406,150.639 145.439,150.632 145.456,150.634 145.472,150.639 145.502,150.66 145.53,150.687 145.55,150.718 145.555,150.733 145.558,150.751 145.55,150.784
  Top Layer w0.241: 144.989,151.201 145.644,150.548 184.169,150.548 184.867,149.849
  Top Layer w0.635: 184.867,149.849 195.345,139.372 pad.1@195.345,137.086
$Net99: pad.1@197.885,137.086 | length 83.8
  Top Layer w0.03: 144.776,152.006 145.045,152.006 ; 144.778,151.99 145.06,151.99 ; 144.781,151.975 145.075,151.975 ; 144.788,151.96 145.091,151.96 ; 144.791,152.051 144.999,152.051 ; 144.801,151.945 145.106,151.945 ; 144.816,151.93 145.121,151.93 ; 144.816,152.082 144.969,152.082 ; 144.832,151.914 145.136,151.914 ; 144.834,152.097 144.953,152.097 ; 144.847,151.899 145.152,151.899 ; 144.857,152.112 144.931,152.112 ; 144.862,151.884 145.167,151.884 ; 144.877,151.869 145.182,151.869 ; 144.893,151.853 145.197,151.853 ; 144.908,151.838 145.213,151.838 ; 144.923,151.823 145.228,151.823 ; 144.938,151.808 145.243,151.808 ; 144.953,151.792 145.258,151.792 ; 144.969,151.777 145.274,151.777 ; 144.984,151.762 145.289,151.762 ; 144.984,152.067 144.801,152.067 ; 144.999,151.747 145.304,151.747 ; 145.014,151.731 145.319,151.731 ; 145.014,152.036 144.781,152.036 ; 145.03,151.716 145.334,151.716 ; 145.03,152.021 144.776,152.021 ; 145.045,151.701 145.35,151.701 ; 145.06,151.686 145.365,151.686 ; 145.075,151.67 145.38,151.67 ; 145.091,151.655 145.395,151.655 ; 145.106,151.64 145.411,151.64 ; 145.121,151.625 145.426,151.625 ; 145.136,151.609 145.439,151.609 ; 145.152,151.594 145.454,151.594 ; 145.167,151.579 145.469,151.579 ; 145.182,151.564 145.484,151.564 ; 145.197,151.549 145.5,151.549 ; 145.213,151.533 145.515,151.533 ; 145.228,151.518 145.53,151.518 ; 145.243,151.503 145.545,151.503 ; 145.258,151.488 145.561,151.488 ; 145.271,151.472 145.576,151.472 ; 145.286,151.457 145.591,151.457 ; 145.301,151.442 145.606,151.442 ; 145.317,151.427 145.622,151.427 ; 145.332,151.411 145.637,151.411 ; 145.347,151.396 145.652,151.396 ; 145.362,151.381 145.667,151.381 ; 145.378,151.366 145.682,151.366 ; 145.393,151.35 145.698,151.35 ; 145.408,151.335 145.713,151.335 ; 145.423,151.32 145.728,151.32 ; 145.439,151.305 145.743,151.305 ; 145.454,151.289 145.759,151.289 ; 145.469,151.274 145.774,151.274 ; 145.484,151.259 145.789,151.259 ; 145.5,151.244 145.804,151.244 ; 145.515,151.228 145.82,151.228 ; 145.53,151.213 145.835,151.213 ; 145.545,151.198 145.85,151.198 ; 145.561,151.183 145.865,151.183 ; 145.576,151.168 145.881,151.168 ; 145.591,151.152 145.896,151.152 ; 145.606,151.137 145.903,151.137 ; 145.622,151.122 145.909,151.122 ; 145.637,151.107 145.911,151.107 ; 145.652,151.091 145.911,151.091 ; 145.667,151.076 145.906,151.076 ; 145.682,151.061 145.898,151.061 ; 145.698,151.046 145.888,151.046 ; 145.713,151.03 145.873,151.03 ; 145.728,151.015 145.858,151.015 ; 145.837,151 145.743,151 ; 144.776,152.021 144.781,152.036 ; 144.776,152.021 144.773,152.003 144.781,151.97 144.788,151.957 145.731,151.01 145.743,151 ; 144.781,152.036 144.801,152.067 ; 144.801,152.067 144.829,152.095 144.86,152.115 144.875,152.12 144.893,152.123 144.926,152.115 144.941,152.107 144.953,152.097 ; 144.953,152.097 145.896,151.15 145.903,151.137 ; 145.743,151 145.759,150.992 145.792,150.985 145.809,150.987 145.825,150.992 145.855,151.013 145.883,151.041 145.903,151.071 145.909,151.086 145.911,151.104 145.903,151.137
  Top Layer w0.241: 145.342,151.554 145.842,151.056 186.201,151.056 186.836,150.421
  Top Layer w0.635: 186.836,150.421 197.885,139.372 pad.1@197.885,137.086
copper on no net: | length 56.5
  Top Layer w0.33: 72.894,142.039 73.96,142.039 73.605,142.356 ; 73.046,162.537 74.113,161.584 ; 73.071,143.786 72.894,143.626 72.894,143.151 73.071,142.991 73.427,142.991 73.605,143.151 73.605,143.786 73.96,143.786 73.96,142.991 ; 73.224,163.649 73.046,163.489 73.046,163.014 73.224,162.854 73.579,162.854 73.757,163.014 73.757,163.649 74.113,163.649 74.113,162.854 ; 197.478,142.674 198.545,141.721 ; 197.478,143.944 198.545,142.991 ; 197.478,144.579 198.545,144.579 198.189,144.896 ; 197.478,163.375 198.545,163.375 198.189,163.692 ; 73.046,161.744 73.046,162.379 73.224,162.537 73.935,162.537 74.113,162.379 74.113,161.744 73.935,161.584 73.224,161.584 73.046,161.744 ; 197.478,141.881 197.478,142.516 197.656,142.674 198.367,142.674 198.545,142.516 198.545,141.881 198.367,141.721 197.656,141.721 197.478,141.881 ; 197.478,143.151 197.478,143.786 197.656,143.944 198.367,143.944 198.545,143.786 198.545,143.151 198.367,142.991 197.656,142.991 197.478,143.151
  Top Layer w0.457: 193.744,152.453 193.744,153.405 194.303,153.405 194.583,153.215 194.583,152.643 194.862,152.453 195.141,152.453 195.421,152.643 195.421,153.215 195.141,153.405 ; 193.744,156.644 195.421,156.644 195.421,155.691 195.141,155.501 194.862,155.501 194.583,155.691 194.583,156.644 ; 193.744,157.025 193.744,158.168 195.421,158.168 ; 194.024,151.881 193.744,151.691 193.744,151.119 194.024,150.929 194.303,150.929 194.583,151.119 ; 194.024,153.977 193.744,154.167 193.744,154.739 194.303,155.12 194.862,155.12 195.421,154.739 195.421,154.167 195.141,153.977 ; 194.583,150.357 194.583,149.595 194.303,149.405 194.024,149.405 193.744,149.595 193.744,150.167 194.024,150.357 195.141,150.357 195.421,150.167 195.421,149.595 195.141,149.405 ; 194.583,151.5 194.583,151.119 ; 195.141,151.881 195.421,151.691 195.421,151.119 195.141,150.929 194.862,150.929 194.583,151.119 ; 194.583,148.071 194.303,147.881 194.024,147.881 193.744,148.071 193.744,148.643 194.024,148.833 194.303,148.833 194.583,148.643 ; 194.583,148.071 194.583,148.643 ; 194.583,148.071 194.862,147.881 195.141,147.881 195.421,148.071 195.421,148.643 195.141,148.833 194.862,148.833 194.583,148.643

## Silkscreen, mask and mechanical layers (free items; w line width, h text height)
Top Overlay:
  lines w0.198: 144.705,152.542 135.657,143.494 126.394,152.758 135.657,162.021 144.705,152.973
  lines w0.203: 144.707,152.542 144.707,152.973 ; 97.557,135.816 97.557,138.356 ; 97.557,135.816 122.957,135.816 ; 97.557,135.816 97.557,138.356 ; 97.557,135.816 72.157,135.816 72.157,138.356 97.557,138.356 ; 97.557,138.356 122.957,138.356 ; 97.557,167.185 97.557,169.725 ; 97.557,167.185 122.957,167.185 ; 97.557,167.185 97.557,169.725 ; 97.557,167.185 72.157,167.185 72.157,169.725 97.557,169.725 ; 97.557,169.725 122.957,169.725 ; 122.957,135.816 122.957,138.356 ; 122.957,135.816 148.357,135.816 ; 122.957,135.816 122.957,138.356 ; 122.957,138.356 148.357,138.356 ; 122.957,167.185 122.957,169.725 ; 122.957,167.185 148.357,167.185 ; 122.957,167.185 122.957,169.725 ; 122.957,169.725 148.357,169.725 ; 148.357,135.816 148.357,138.356 ; 148.357,135.816 173.757,135.816 ; 148.357,135.816 148.357,138.356 ; 148.357,138.356 173.757,138.356 ; 148.357,167.185 148.357,169.725 ; 148.357,167.185 173.757,167.185 ; 148.357,167.185 148.357,169.725 ; 148.357,169.725 173.757,169.725 ; 173.757,135.816 173.757,138.356 ; 173.757,135.816 199.155,135.816 199.155,138.356 173.757,138.356 ; 173.757,135.816 173.757,138.356 ; 173.757,167.185 173.757,169.725 ; 173.757,167.185 199.155,167.185 199.155,169.725 173.757,169.725 ; 173.757,167.185 173.757,169.725
  lines w0.244: 143.061,152.725 143.074,152.653 143.097,152.582 143.135,152.511 143.196,152.44 143.267,152.382 143.338,152.346 143.409,152.323 143.48,152.313 143.506,152.313 143.531,152.313 143.602,152.323 143.673,152.346 143.744,152.382 143.816,152.44 143.877,152.511 143.915,152.582 143.937,152.653 143.95,152.725 143.95,152.758 143.95,152.791 143.937,152.862 143.915,152.933 143.877,153.004 143.816,153.075 143.744,153.133 143.673,153.169 143.602,153.192 143.531,153.202 143.506,153.202 143.48,153.202 143.409,153.192 143.338,153.169 143.267,153.133 143.196,153.075 143.135,153.004 143.097,152.933 143.074,152.862 143.061,152.791 143.061,152.758 143.061,152.725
